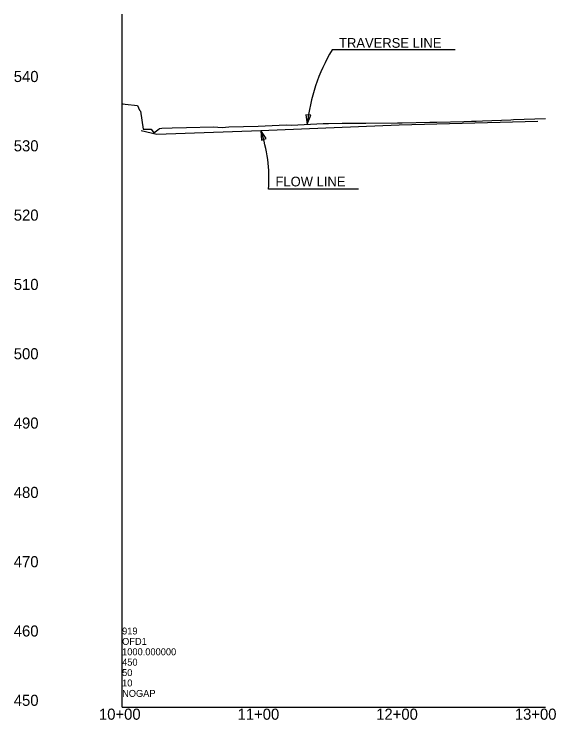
# Model space of a CAD drawing. Extents: x 49922 to 54713, y 49991 to 62800.
# Drawn here: x 49922 to 50313, y 55991 to 56500 of the extents above; entities that cross this region are included whole.
import ezdxf

# ---------------------------------------------------------------- set-up
doc = ezdxf.new("R2010")
doc.units = 0
for name, color, linetype in [('RD_DDB_ElevTX', 7, 'Continuous'), ('RD_DDB_Profile_EX', 7, 'Continuous'), ('RD_DDB_StaTX', 7, 'Continuous'), ('RD_GPK_Profile_Cell', 7, 'Continuous'), ('RD_TX_Profile', 7, 'Continuous')]:
    doc.layers.add(name, color=color, linetype=linetype)

msp = doc.modelspace()

# ---------------------------------------------------------------- linework, layer by layer
at = {"layer": 'RD_DDB_Profile_EX'}
for points in [[(50000, 56435.12), (50000.68, 56435.22), (50002.22, 56435.03), (50011.14, 56434), (50012.68, 56430.8), (50013.23, 56429.99), (50015.21, 56417.09), (50020.88, 56417.03), (50022.88, 56414.45), (50026.7, 56417.33), (50027.05, 56417.59), (50028.57, 56417.78), (50036.04, 56417.91), (50046.48, 56418.18), (50065.83, 56418.68), (50072.2, 56418.31), (50077.06, 56418.69), (50098.26, 56419.22), (50118.38, 56420.06), (50122.1, 56419.91), (50145.12, 56421.12), (50148.86, 56421.17), (50158.73, 56421.3), (50173.84, 56421.38), (50175.95, 56421.41), (50198.76, 56421.56), (50199.59, 56421.57), (50202.16, 56421.63), (50221.96, 56422.08), (50227.16, 56422.16), (50246.5, 56422.6), (50252.17, 56422.68), (50254.75, 56422.78), (50255.38, 56422.81), (50259.89, 56423.05), (50280.39, 56423.8), (50282.46, 56423.9), (50305.4, 56424.73)], [(50013.73, 56416.15), (50025, 56413.45), (50100, 56416.15), (50200, 56420.2), (50300, 56422.8)]]:
    msp.add_lwpolyline(points, dxfattribs=at)
at = {"layer": 'RD_GPK_Profile_Cell'}
for q in [(50000, 56500), (50305.4, 56000), (50000, 56000)]:
    msp.add_line((50000, 56000), q, dxfattribs=at)
at = {"layer": 'RD_TX_Profile'}
for p, q in [((50240.37, 56474.23), (50151.53, 56474.23)), ((50170.52, 56373.72), (50105.68, 56373.72))]:
    msp.add_line(p, q, dxfattribs=at)
for points in [[(50132.51, 56427.43), (50133.61, 56420.51), (50136.11, 56427.05)], [(50103.97, 56410.38), (50100, 56416.15), (50100.55, 56409.17)]]:
    msp.add_lwpolyline(points, close=True, dxfattribs=at)
for centre, radius, start, end in [((50263.63, 56406.99), 130.73, 149.0438, 174.061), ((50002.11, 56381.45), 103.86, 355.7316, 19.5164)]:
    msp.add_arc(centre, radius, start, end, dxfattribs=at)

# ---------------------------------------------------------------- texts
at = {"layer": 'RD_DDB_ElevTX'}
for s, p in [('540', (49921.86, 56451)), ('530', (49921.86, 56401)), ('520', (49921.86, 56351)), ('510', (49921.86, 56301)), ('500', (49921.86, 56251)), ('490', (49921.86, 56201)), ('480', (49921.86, 56151)), ('470', (49921.86, 56101)), ('460', (49921.86, 56051)), ('450', (49921.86, 56001))]:
    msp.add_text(s, height=8, dxfattribs=at).set_placement(p)
at = {"layer": 'RD_DDB_StaTX'}
for s, p in [('10+00', (49983.32, 55991)), ('11+00', (50083.32, 55991)), ('12+00', (50183.32, 55991)), ('13+00', (50283.32, 55991))]:
    msp.add_text(s, height=8, dxfattribs=at).set_placement(p)
at = {"layer": 'RD_GPK_Profile_Cell'}
for s, p in [('919', (50000, 56052.5)), ('OFD1', (50000, 56045)), ('1000.000000', (50000, 56037.5)), ('450', (50000, 56030)), ('50', (50000, 56022.5)), ('10', (50000, 56015)), ('NOGAP', (50000, 56007.5))]:
    msp.add_text(s, height=5, dxfattribs=at).set_placement(p)
at = {"layer": 'RD_TX_Profile'}
for s, p in [('TRAVERSE LINE', (50156.53, 56475.73)), ('FLOW LINE', (50110.68, 56375.72))]:
    msp.add_text(s, height=7, dxfattribs=at).set_placement(p)

doc.saveas('drawing.dxf')
